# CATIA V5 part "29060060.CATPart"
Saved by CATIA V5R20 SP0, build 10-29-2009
Part number: 29060060
Definition: NONE
Nomenclature: 29060060
Source: Unknown
Description: 29060060
Bounding box of the stored display mesh (mm): x -30 to 44.548, y -44 to 78.548, z -34 to 34
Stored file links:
  C:\Users\Utente\Desktop\IO LAVORO\3D X SITO CF\X SITO\PLASTICA\RF1\29060060.CATPart
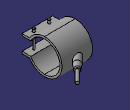
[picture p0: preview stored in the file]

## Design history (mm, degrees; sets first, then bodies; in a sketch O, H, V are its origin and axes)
Body1 "29060060" (main body)
  Solid1: solid without history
